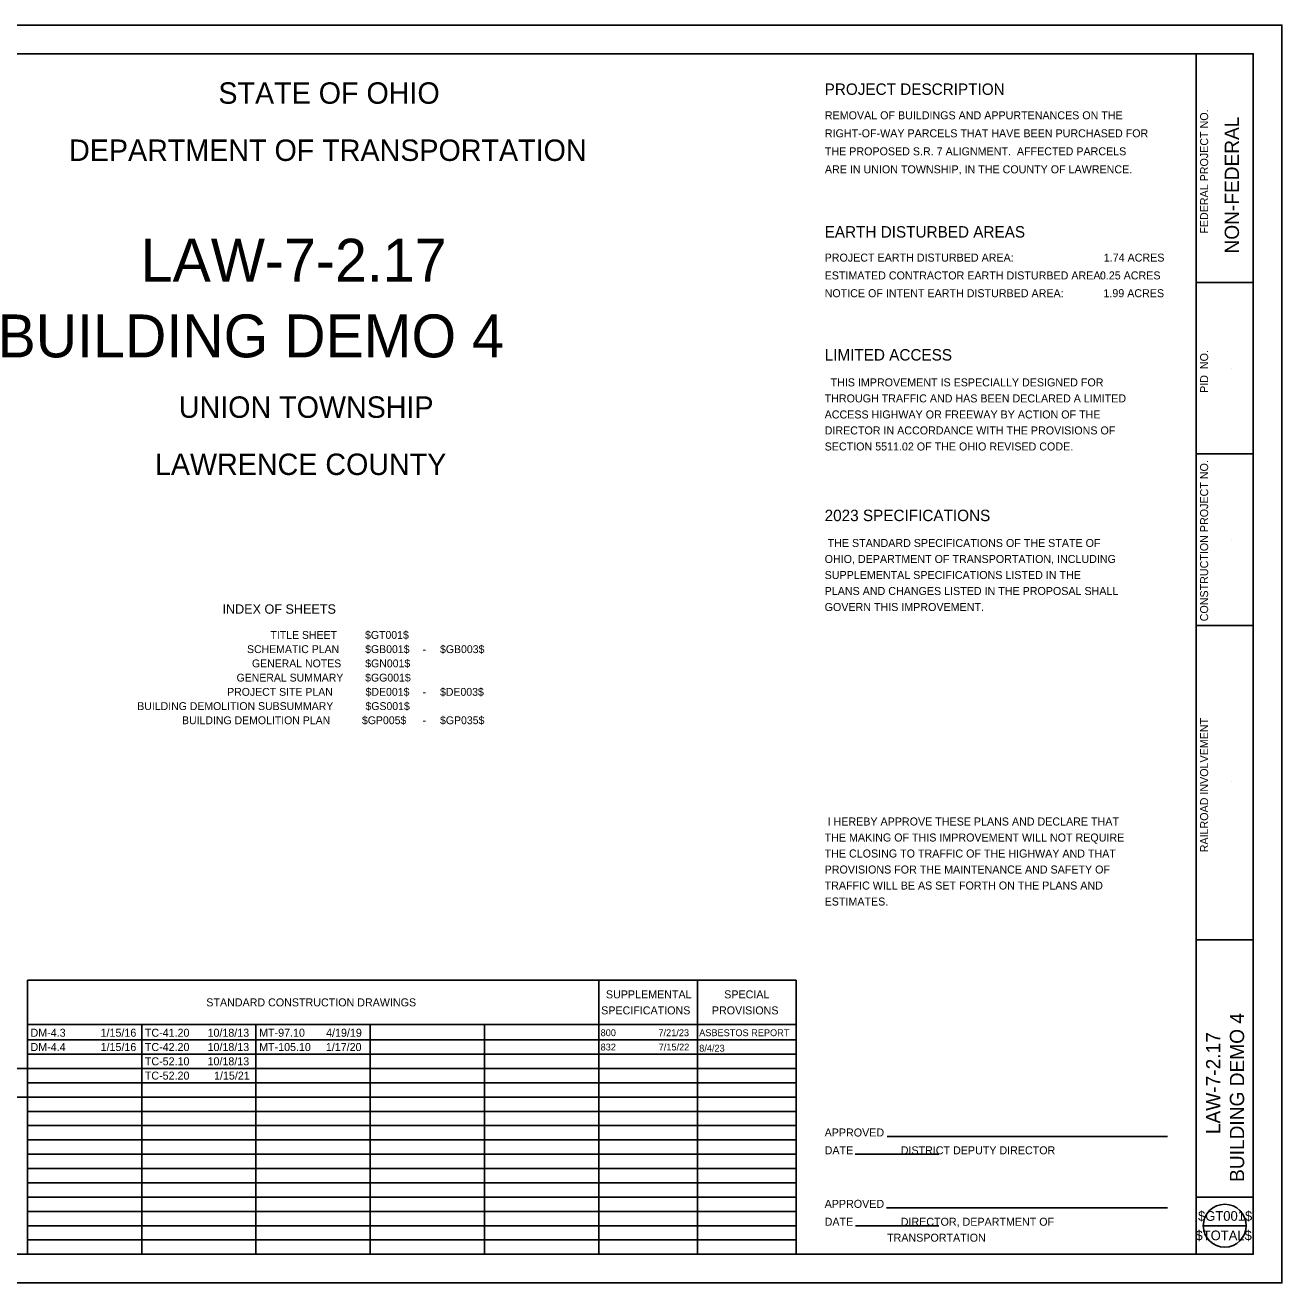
# Model space of a CAD drawing. Extents: x 0 to 34, y 0 to 22.
# Drawn here: x 12.01 to 34, y 0 to 22 of the extents above; entities that cross this region are included whole.
import ezdxf

# ---------------------------------------------------------------- set-up
doc = ezdxf.new("R2010")
doc.units = 0
for name, color, linetype in [('SH_Border', 7, 'Continuous'), ('SH_Cut_Line', 7, 'Continuous'), ('SH_Data', 7, 'Continuous'), ('SH_Text', 7, 'Continuous')]:
    doc.layers.add(name, color=color, linetype=linetype)

msp = doc.modelspace()

# ---------------------------------------------------------------- linework, layer by layer
at = {"layer": 'SH_Border'}
for p, q in [((32.5, 0.5), (32.5, 21.5)), ((32.5, 17.5), (33.5, 17.5)), ((32.5, 14.5), (33.5, 14.5)), ((32.5, 11.5), (33.5, 11.5)), ((32.5, 6), (33.5, 6)), ((32.5, 1.5), (33.5, 1.5))]:
    msp.add_line(p, q, dxfattribs=at)
msp.add_lwpolyline([(2, 21.5), (33.5, 21.5), (33.5, 0.5), (2, 0.5)], close=True, dxfattribs=at)
at = {"layer": 'SH_Cut_Line'}
msp.add_lwpolyline([(0, 0), (34, 0), (34, 22), (0, 22)], close=True, dxfattribs=at)
at = {"layer": 'SH_Data'}
for p, q in [((33.125, 19.5), (33.125, 19.5)), ((33.125, 16), (33.125, 16)), ((33.125, 13), (33.125, 13)), ((33.125, 8.766), (33.125, 8.766)), ((12.05, 5.292), (25.5, 5.292)), ((12.05, 0.5), (12.05, 5.292)), ((22.05, 0.5), (22.05, 5.292)), ((23.775, 0.5), (23.775, 5.292)), ((25.5, 0.5), (25.5, 5.292)), ((12.05, 4.521), (25.5, 4.521)), ((14.05, 0.5), (14.05, 4.521)), ((16.05, 0.5), (16.05, 4.521)), ((18.05, 0.5), (18.05, 4.521)), ((20.05, 0.5), (20.05, 4.521)), ((12.05, 4.25), (25.5, 4.25)), ((12.05, 4), (25.5, 4)), ((9.25, 3.75), (12.05, 3.75)), ((12.05, 3.75), (25.5, 3.75)), ((33, 3.799), (33, 3.799)), ((12.05, 3.5), (25.5, 3.5)), ((9.25, 3.25), (12.05, 3.25)), ((12.05, 3.25), (25.5, 3.25)), ((12.05, 3), (25.5, 3)), ((12.05, 2.75), (25.5, 2.75)), ((12.05, 2.5), (25.5, 2.5)), ((27.095, 2.56), (32, 2.56)), ((12.05, 2.25), (25.5, 2.25)), ((26.533, 2.248), (28, 2.248)), ((12.05, 2), (25.5, 2)), ((12.05, 1.75), (25.5, 1.75)), ((12.05, 1.5), (25.5, 1.5)), ((12.05, 1.25), (25.5, 1.25)), ((27.08, 1.312), (32, 1.312)), ((12.05, 1), (25.5, 1)), ((26.542, 0.999), (28, 0.999)), ((32.625, 1), (33.375, 1)), ((33, 1.085), (33, 1.085)), ((12.05, 0.75), (25.5, 0.75)), ((33, 0.745), (33, 0.745))]:
    msp.add_line(p, q, dxfattribs=at)
msp.add_circle((33, 1), 0.375, dxfattribs=at)

# ---------------------------------------------------------------- texts
for s, height, p in [('STATE OF OHIO', 0.375, (15.392, 20.625)), ('PROJECT DESCRIPTION', 0.2, (26, 20.78)), ('REMOVAL OF BUILDINGS AND APPURTENANCES ON THE', 0.14, (26.004, 20.353)), ('RIGHT-OF-WAY PARCELS THAT HAVE BEEN PURCHASED FOR', 0.14, (26.004, 20.038)), ('DEPARTMENT OF TRANSPORTATION', 0.375, (12.78, 19.625)), ('THE PROPOSED S.R. 7 ALIGNMENT.  AFFECTED PARCELS', 0.14, (26.004, 19.723)), ('ARE IN UNION TOWNSHIP, IN THE COUNTY OF LAWRENCE.', 0.14, (26.004, 19.408)), ('EARTH DISTURBED AREAS', 0.2, (26, 18.284)), ('LAW-7-2.17', 0.75, (14.033, 17.513)), ('PROJECT EARTH DISTURBED AREA:', 0.14, (26, 17.864)), ('1.74 ACRES', 0.14, (30.884, 17.864)), ('ESTIMATED CONTRACTOR EARTH DISTURBED AREA:', 0.14, (26, 17.552)), ('0.25 ACRES', 0.14, (30.816, 17.552)), ('NOTICE OF INTENT EARTH DISTURBED AREA:', 0.14, (26, 17.241)), ('1.99 ACRES', 0.14, (30.878, 17.241)), ('BUILDING DEMO 4', 0.75, (11.527, 16.189)), ('LIMITED ACCESS', 0.2, (26, 16.133)), ('  THIS IMPROVEMENT IS ESPECIALLY DESIGNED FOR', 0.14, (26, 15.681)), ('UNION TOWNSHIP', 0.375, (14.7, 15.131)), ('THROUGH TRAFFIC AND HAS BEEN DECLARED A LIMITED', 0.14, (26, 15.401)), ('ACCESS HIGHWAY OR FREEWAY BY ACTION OF THE', 0.14, (26, 15.12)), ('DIRECTOR IN ACCORDANCE WITH THE PROVISIONS OF', 0.14, (26, 14.841)), ('SECTION 5511.02 OF THE OHIO REVISED CODE.', 0.14, (26, 14.56)), ('LAWRENCE COUNTY', 0.375, (14.282, 14.131)), ('2023 SPECIFICATIONS', 0.2, (26, 13.324)), (' THE STANDARD SPECIFICATIONS OF THE STATE OF', 0.14, (26, 12.872)), ('OHIO, DEPARTMENT OF TRANSPORTATION, INCLUDING', 0.14, (26, 12.592)), ('SUPPLEMENTAL SPECIFICATIONS LISTED IN THE', 0.14, (26, 12.312)), ('PLANS AND CHANGES LISTED IN THE PROPOSAL SHALL', 0.14, (26, 12.032)), ('GOVERN THIS IMPROVEMENT.', 0.14, (26, 11.752)), (' I HEREBY APPROVE THESE PLANS AND DECLARE THAT', 0.14, (26, 8)), ('THE MAKING OF THIS IMPROVEMENT WILL NOT REQUIRE', 0.14, (26, 7.72)), ('THE CLOSING TO TRAFFIC OF THE HIGHWAY AND THAT', 0.14, (26, 7.44)), ('PROVISIONS FOR THE MAINTENANCE AND SAFETY OF', 0.14, (26, 7.16)), ('TRAFFIC WILL BE AS SET FORTH ON THE PLANS AND', 0.14, (26, 6.88)), ('ESTIMATES.', 0.14, (26, 6.6)), ('SUPPLEMENTAL', 0.14, (22.173, 4.976)), ('SPECIAL', 0.14, (24.243, 4.976)), ('STANDARD CONSTRUCTION DRAWINGS', 0.14, (15.18, 4.836)), ('SPECIFICATIONS', 0.14, (22.09, 4.696)), ('PROVISIONS', 0.14, (24.027, 4.696)), ('DM-4.3', 0.14, (12.105, 4.305)), ('1/15/16', 0.14, (13.331, 4.305)), ('TC-41.20', 0.14, (14.105, 4.305)), ('10/18/13', 0.14, (15.202, 4.305)), ('MT-97.10', 0.14, (16.105, 4.305)), ('4/19/19', 0.14, (17.277, 4.305)), ('800', 0.12, (22.08, 4.315)), ('7/21/23', 0.12, (23.092, 4.315)), ('ASBESTOS REPORT', 0.12, (23.805, 4.315)), ('DM-4.4', 0.14, (12.105, 4.055)), ('1/15/16', 0.14, (13.331, 4.055)), ('TC-42.20', 0.14, (14.105, 4.055)), ('10/18/13', 0.14, (15.202, 4.055)), ('MT-105.10', 0.14, (16.105, 4.055)), ('1/17/20', 0.14, (17.272, 4.055)), ('832', 0.12, (22.08, 4.065)), ('7/15/22', 0.12, (23.096, 4.065)), ('8/4/23', 0.12, (23.805, 4.044)), ('TC-52.10', 0.14, (14.105, 3.805)), ('10/18/13', 0.14, (15.202, 3.805)), ('TC-52.20', 0.14, (14.105, 3.555)), ('1/15/21', 0.14, (15.316, 3.555)), ('APPROVED', 0.14, (26, 2.56)), ('DATE                DISTRICT DEPUTY DIRECTOR', 0.14, (26, 2.248)), ('APPROVED', 0.14, (26, 1.312)), ('DATE                DIRECTOR, DEPARTMENT OF', 0.14, (26, 0.999)), ('$GT001$', 0.17, (32.533, 1.085)), ('$TOTAL$', 0.17, (32.489, 0.745)), ('                     TRANSPORTATION', 0.14, (26, 0.72))]:
    msp.add_text(s, height=height, dxfattribs=at).set_placement(p)
for s, height, p in [('FEDERAL PROJECT NO.', 0.14, (32.71, 18.352)), ('NON-FEDERAL', 0.25, (33.25, 18.005)), ('PID  NO.', 0.14, (32.71, 15.567)), ('CONSTRUCTION PROJECT NO.', 0.14, (32.71, 11.572)), ('RAILROAD INVOLVEMENT', 0.14, (32.71, 7.531)), ('BUILDING DEMO 4', 0.25, (33.34, 1.766)), ('LAW-7-2.17', 0.25, (32.924, 2.601))]:
    msp.add_text(s, height=height, rotation=90, dxfattribs=at).set_placement(p)
at = {"layer": 'SH_Text'}
for s, height, p in [('INDEX OF SHEETS', 0.16486, (15.464, 11.704)), ('TITLE SHEET', 0.13738, (16.303, 11.265)), ('$GT001$', 0.1374, (17.958, 11.265)), ('SCHEMATIC PLAN', 0.13738, (15.893, 11.016)), ('$GB001$', 0.1374, (17.96, 11.016)), ('-', 0.137, (18.966, 11.016)), ('$GB003$', 0.1374, (19.27, 11.016)), ('GENERAL NOTES', 0.13738, (15.979, 10.767)), ('$GN001$', 0.1374, (17.962, 10.767)), ('GENERAL SUMMARY', 0.13738, (15.71, 10.518)), ('$GG001$', 0.1374, (17.96, 10.518)), ('PROJECT SITE PLAN', 0.13738, (15.546, 10.269)), ('$DE001$', 0.1374, (17.968, 10.269)), ('$DE003$', 0.1374, (19.27, 10.269)), ('BUILDING DEMOLITION SUBSUMMARY', 0.13738, (13.973, 10.02)), ('$GS001$', 0.1374, (17.965, 10.02)), ('-', 0.137, (18.966, 10.269)), ('BUILDING DEMOLITION PLAN', 0.13738, (14.756, 9.772)), ('$GP005$', 0.1374, (17.904, 9.772)), ('$GP035$', 0.1374, (19.27, 9.772)), ('-', 0.137, (18.966, 9.772))]:
    msp.add_text(s, height=height, dxfattribs=at).set_placement(p)

doc.saveas('drawing.dxf')
